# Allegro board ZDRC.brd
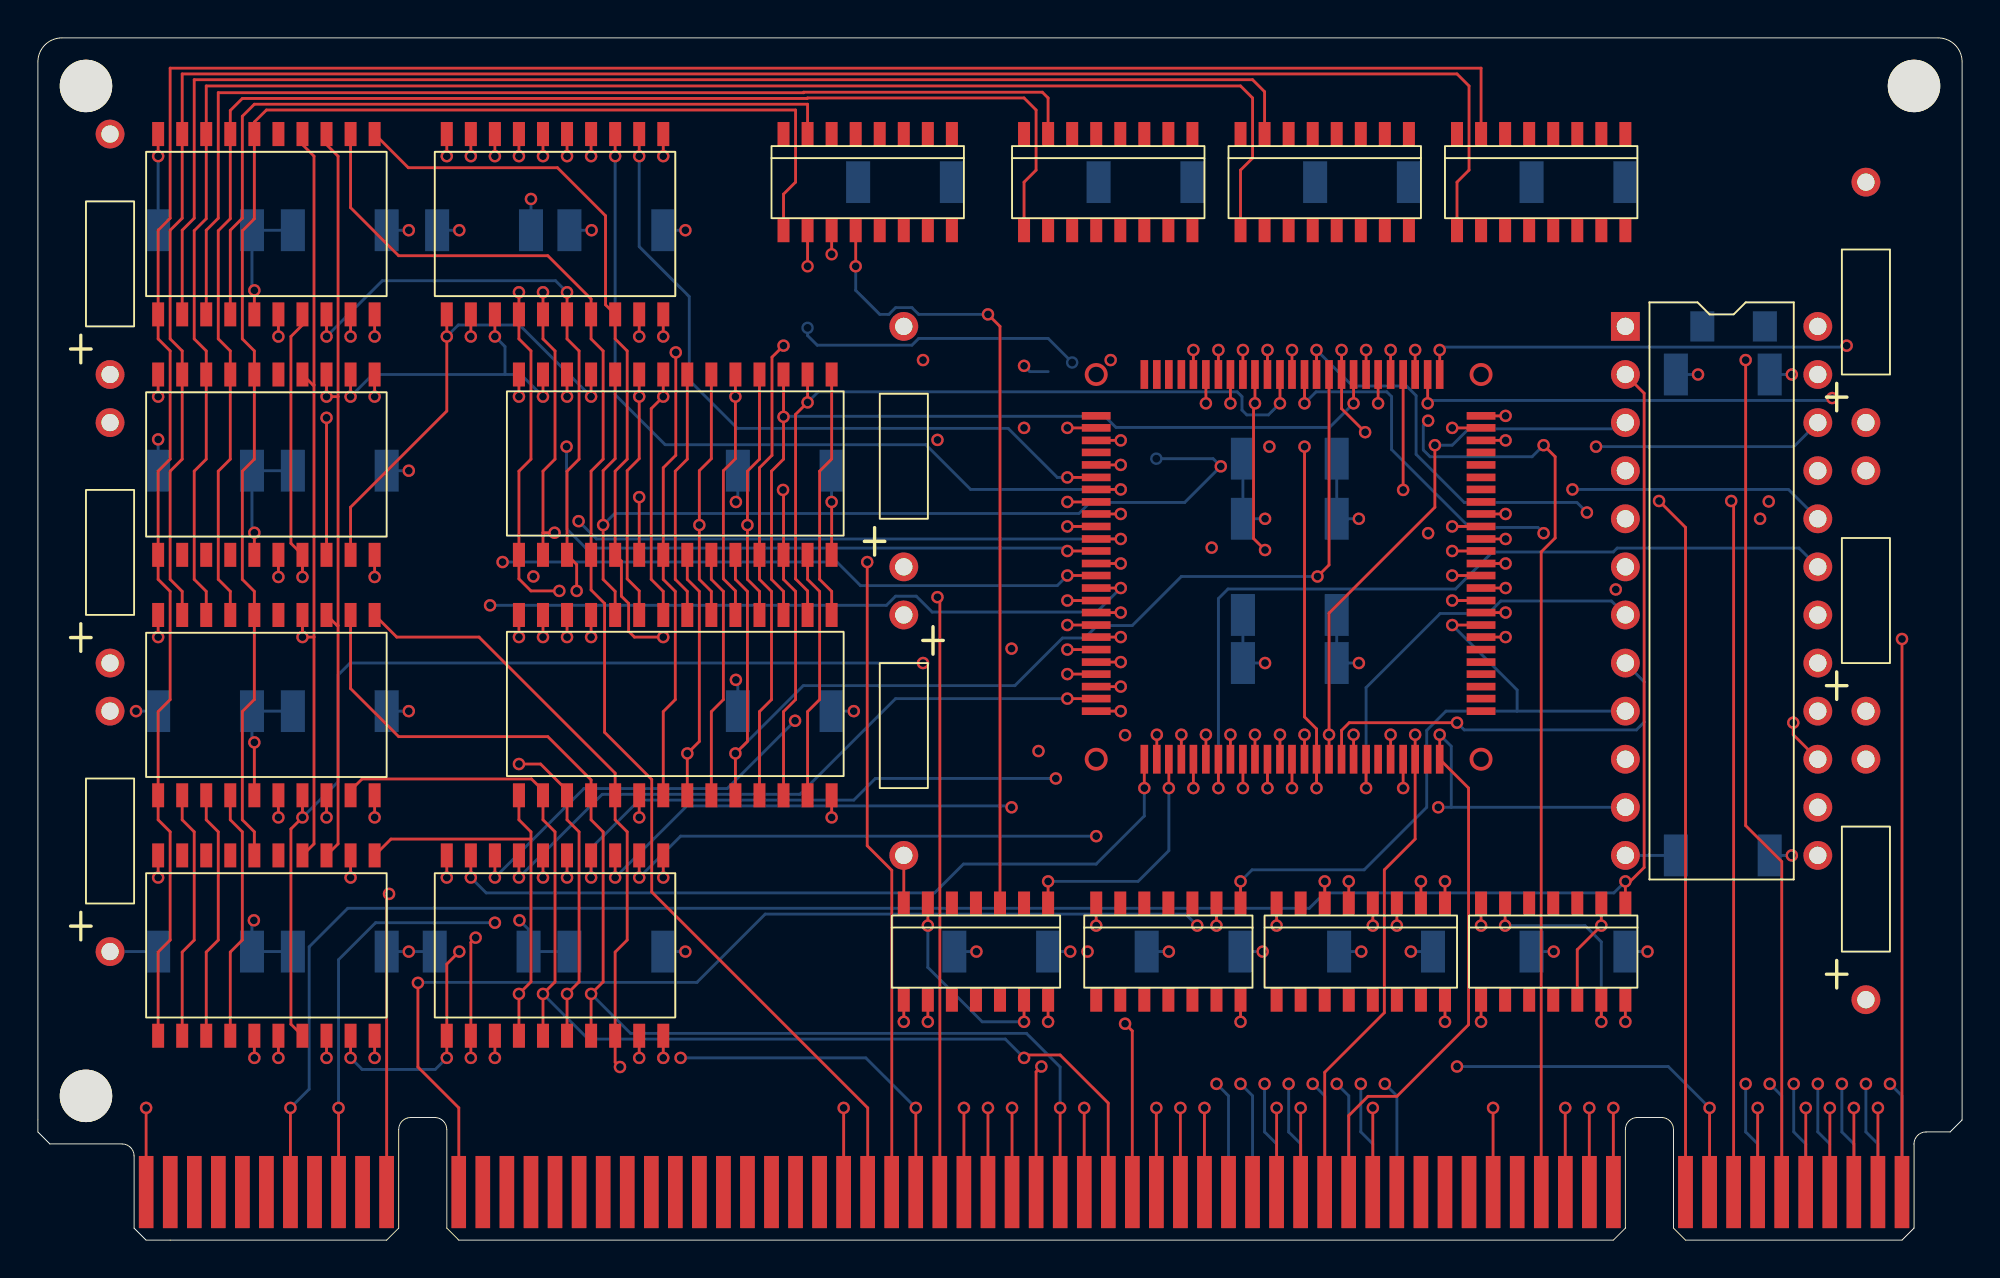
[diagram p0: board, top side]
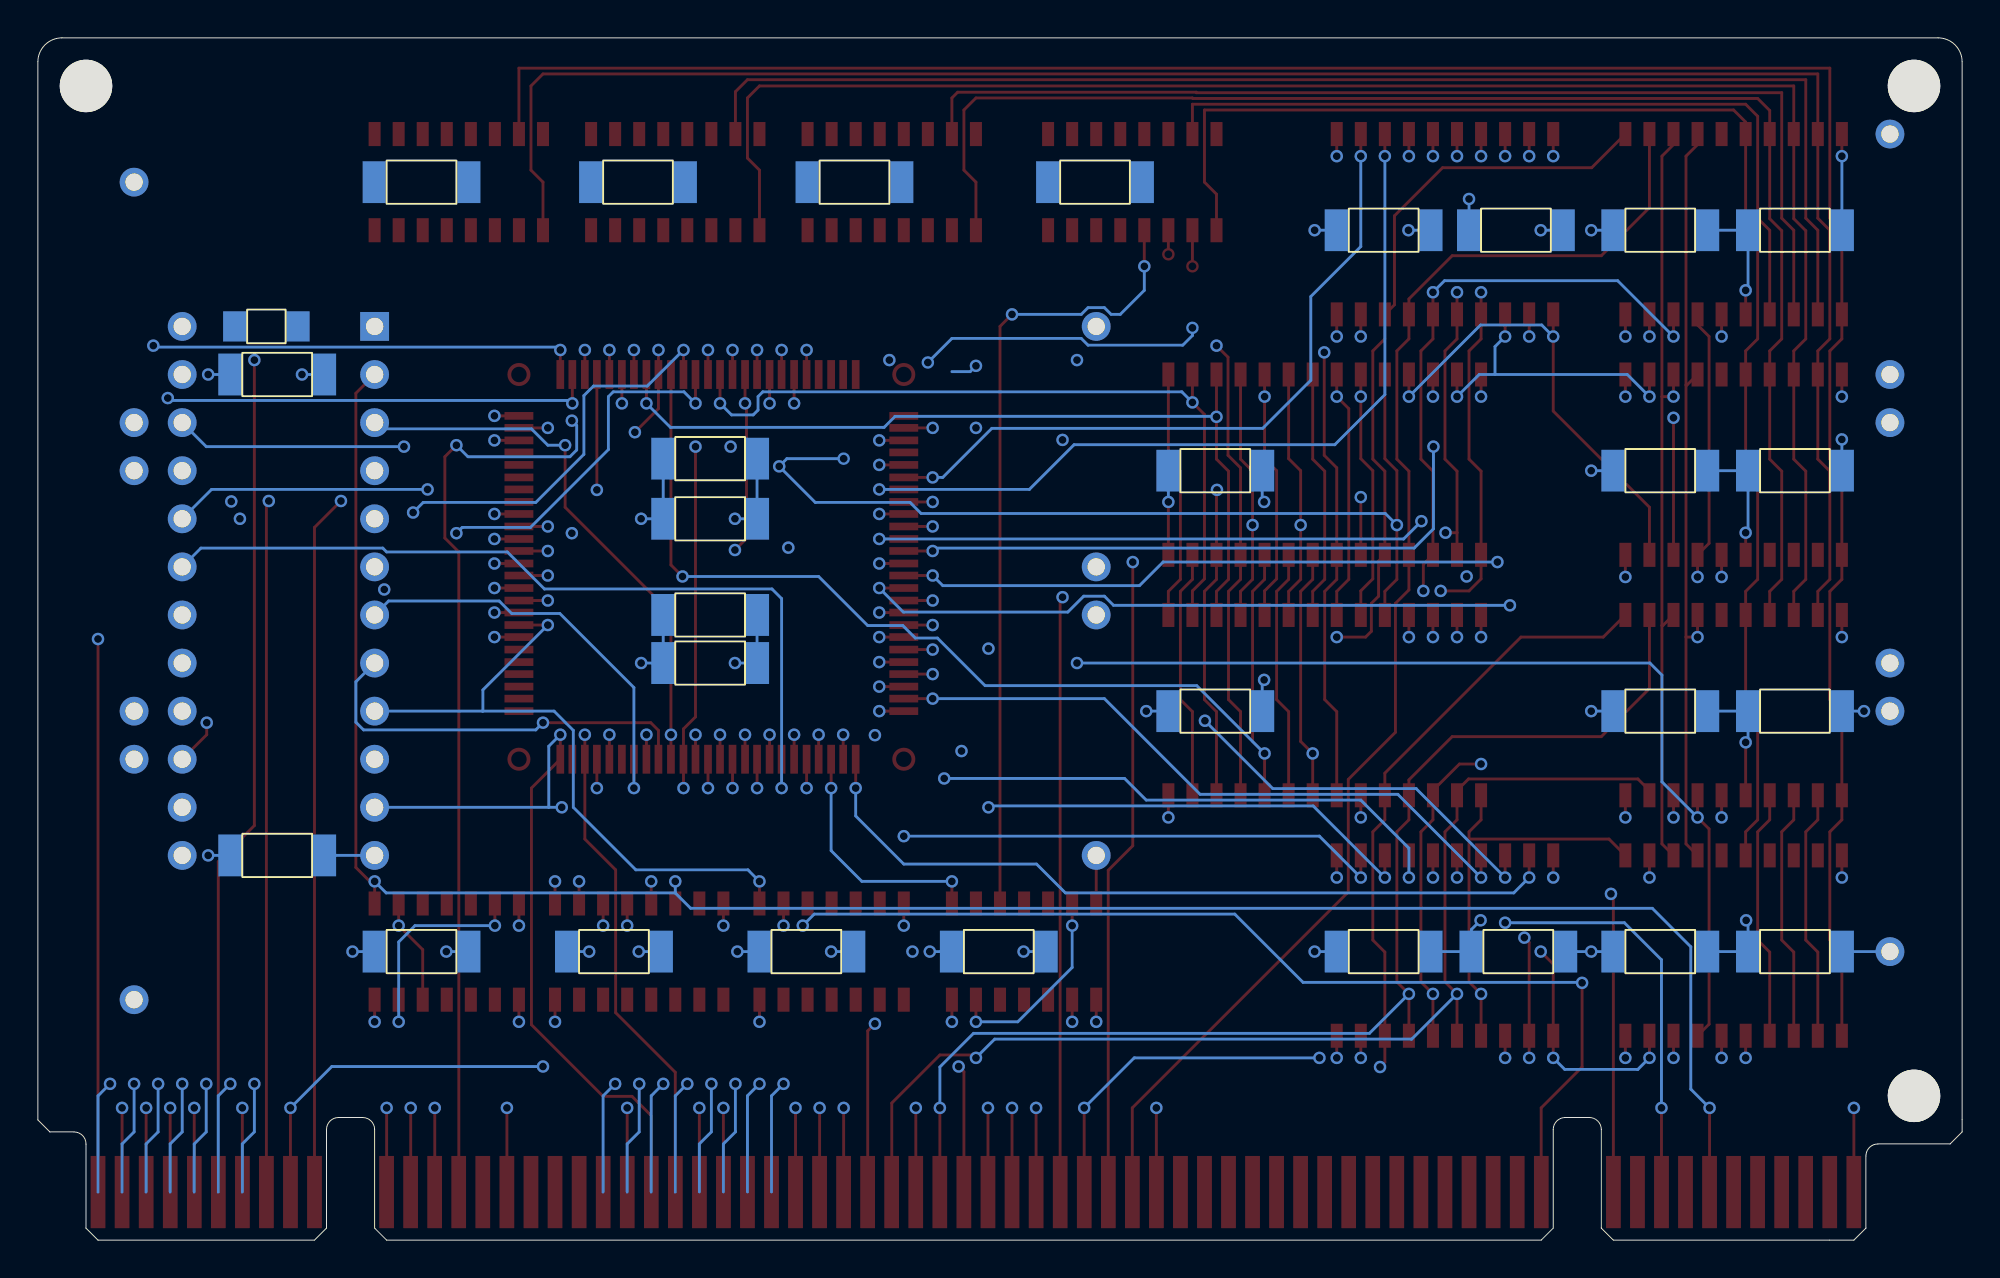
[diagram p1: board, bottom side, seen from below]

Outline 101.6 x 63.5 mm; copper layers: TOP, GND, IS1, IS2, VCC, GND2, IS3, IS4, GND3, BOTTOM. Coordinates in mm from the lower left corner of the outline.
Outline path: 0,62.23 arc(0.37,63.13) 1.27,63.5 100.33,63.5 arc(101.23,63.13) 101.6,62.23 101.6,6.35 100.97,5.71 99.7,5.71 arc(99.25,5.53) 99.06,5.08 99.06,0.63 98.43,0 87,0 86.36,0.63 86.36,5.84 arc(86.17,6.29) 85.73,6.48 84.46,6.48 arc(84.01,6.29) 83.82,5.84 83.82,0.63 83.19,0 22.22,0 21.59,0.63 21.59,5.84 arc(21.4,6.29) 20.95,6.48 19.68,6.48 arc(19.24,6.29) 19.05,5.84 19.05,0.63 18.41,0 5.71,0 5.08,0.63 5.08,4.45 arc(4.89,4.89) 4.45,5.08 0.64,5.08 0,5.71 0,62.23

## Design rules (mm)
constraint set DEFAULT: min track width 0.152
net group A_GROUP: nets A1 A2 A3 A4 A5 A6 A7 A8 A9 A10 A11 A12 A13 A14 A15 A16 A17 A18 A19 A20 A21 A22 A23
net group RA_GROUP: nets RA0 RA1 RA2 RA3 RA4 RA5 RA6 RA7

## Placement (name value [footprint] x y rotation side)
C1  0.01UF  [SMDCAP]  23.49 53.34 180 bottom
C2  0.01UF  [SMDCAP]  15.88 40.64 180 bottom
C3  0.01UF  [SMDCAP]  15.88 27.94 180 bottom
C4  0.01UF  [SMDCAP]  15.88 53.34 180 bottom
C5  0.01UF  [SMDCAP]  15.88 15.24 180 bottom
C6  0.01UF  [SMDCAP]  88.9 20.32 180 bottom
C7  0.01UF  [SMDCAP]  23.49 15.24 0 bottom
C8  0.01UF  [SMDCAP]  66.04 30.48 180 bottom
C9  0.01UF  [SMDCAP]  66.04 41.27 180 bottom
C10  0.01UF  [SMDCAP]  8.89 53.34 0 bottom
C11  0.01UF  [SMDCAP]  8.89 40.64 0 bottom
C12  0.01UF  [SMDCAP]  8.89 27.94 0 bottom
C13  0.01UF  [SMDCAP]  8.89 15.24 0 bottom
C14  0.01UF  [SMDCAP]  30.48 15.24 180 bottom
C15  0.01UF  [SMDCAP]  30.48 53.34 180 bottom
C16  0.01UF  [SMDCAP]  39.37 40.64 180 bottom
C17  0.01UF  [SMDCAP]  39.37 27.94 180 bottom
C18  0.01UF  [SMDCAP]  66.04 38.1 180 bottom
C19  0.01UF  [SMDCAP]  66.04 33.02 180 bottom
C20  0.01UF  [SMDCAP]  50.8 15.24 180 bottom
C21  0.022UF  [CAP400]  45.72 30.48 180 top
C22  0.022UF  [CAP400]  45.72 38.1 0 top
C23  0.022UF  [CAP400]  96.52 15.24 0 top
C24  0.022UF  [CAP400]  96.52 30.48 0 top
C25  0.022UF  [CAP400]  96.52 45.72 0 top
C26  0.022UF  [CAP400]  3.81 48.26 0 top
C27  0.022UF  [CAP400]  3.81 33.02 0 top
C28  0.022UF  [CAP400]  3.81 17.78 0 top
C29  1UF  [SMDCAP]  60.96 15.24 180 bottom
C30  1UF  [SMDCAP]  71.12 15.24 180 bottom
C31  1UF  [SMDCAP]  81.28 15.24 180 bottom
C32  1UF  [SMDCAP]  45.72 55.88 180 bottom
C33  1UF  [SMDCAP]  58.42 55.88 180 bottom
C34  1UF  [SMDCAP]  69.85 55.88 180 bottom
C35  1UF  [SMDCAP]  81.28 55.88 180 bottom
C36  1UF  [SMDCAP]  88.9 45.72 180 bottom
J1  -  [CONN140]  98.43 2.54 0 top
NOREF  -  [unnamed]  2.54 7.62 0 top
NOREF#2  -  [unnamed]  2.54 60.96 0 top
NOREF#3  -  [unnamed]  99.06 60.96 0 top
R1  10  [SMDRES]  89.54 48.26 180 bottom
U1  ***  [SOIC20W]  12.07 53.97 270 top
U2  ***  [SOIC20W]  12.07 41.27 270 top
U3  ***  [SOIC20W]  12.07 28.57 270 top
U4  ***  [SOIC20W]  12.07 15.88 270 top
U5  ***  [SOIC14]  59.69 15.24 270 top
U6  ***  [SOIC14]  49.53 15.24 270 top
U7  ***  [SOIC16]  69.85 15.24 270 top
U8  ***  [SOIC20W]  27.3 53.97 270 top
U9  ***  [SOIC20W]  27.3 15.88 270 top
U10  ***  [SOIC16]  43.81 55.88 270 top
U11  ***  [SOIC16]  79.38 55.88 270 top
U12  ***  [SOIC16]  56.52 55.88 270 top
U13  ***  [SOIC16]  67.95 55.88 270 top
U14  ***  [SOIC14]  80.01 15.24 270 top
U15  ***  [DIP24_4]  83.82 48.26 0 top
U16  ***  [SOIC28W]  33.66 41.27 270 top
U17  -  [FLAT100]  58.42 25.4 270 top
U18  ***  [SOIC28W]  33.66 28.57 270 top

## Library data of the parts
C1-C20 = CAP-.01UF: User Part Number: 1206; Tolerance: ***
C21-C28 = CAP-22UF: User Part Number: 21505-274-01; Tolerance: ***
C29-C36 = CAP-1UF: User Part Number: 21503-260-12; Tolerance: ***
J1 = CONN140-1
R1 = PRES-10: User Part Number: 24707-008-01; Tolerance: ***
U1-U4 = M5M44C256P-10-1
U5 = 74F04-1
U6 U14 = 74F393-1
U7 = 74F109-1
U8 U9 = 74F245-1
U10-U13 = 74F153-1
U15 = MEMPAL-1
U16 U18 = 27C256-1
U17 = I80386S-1

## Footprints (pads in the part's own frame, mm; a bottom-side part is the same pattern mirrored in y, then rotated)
CAP400
  round 1.524 hole 0.914: 1(0,-2.54) 2(0,10.16)
CONN140
  rect 0.762x3.81 smd: 1(0,0) 2(-1.27,0) 3(-2.54,0) 4(-3.81,0) 5(-5.08,0) 6(-6.35,0) 7(-7.62,0) 8(-8.89,0) 9(-10.16,0) 10(-11.43,0) 11(-15.24,0) 12(-16.51,0) 13(-17.78,0) 14(-19.05,0) 15(-20.32,0) 16(-21.59,0) 17(-22.86,0) 18(-24.13,0) 19(-25.4,0) 20(-26.67,0) 21(-27.94,0) 22(-29.21,0) 23(-30.48,0) 24(-31.75,0) 25(-33.02,0) 26(-34.29,0) 27(-35.56,0) 28(-36.83,0) 29(-38.1,0) 30(-39.37,0) 31(-40.64,0) 32(-41.91,0) 33(-43.18,0) 34(-44.45,0) 35(-45.72,0) 36(-46.99,0) 37(-48.26,0) 38(-49.53,0) 39(-50.8,0) 40(-52.07,0) 41(-53.34,0) 42(-54.61,0) 43(-55.88,0) 44(-57.15,0) 45(-58.42,0) 46(-59.69,0) 47(-60.96,0) 48(-62.23,0) 49(-63.5,0) 50(-64.77,0) 51(-66.04,0) 52(-67.31,0) 53(-68.58,0) 54(-69.85,0) 55(-71.12,0) 56(-72.39,0) 57(-73.66,0) 58(-74.93,0) 59(-76.2,0) 60(-80.01,0) 61(-81.28,0) 62(-82.55,0) 63(-83.82,0) 64(-85.09,0) 65(-86.36,0) 66(-87.63,0) 67(-88.9,0) 68(-90.17,0) 69(-91.44,0) 70(-92.71,0) 71(0,0) 72(-1.27,0) 73(-2.54,0) 74(-3.81,0) 75(-5.08,0) 76(-6.35,0) 77(-7.62,0) 78(-8.89,0) 79(-10.16,0) 80(-11.43,0) 81(-15.24,0) 82(-16.51,0) 83(-17.78,0) 84(-19.05,0) 85(-20.32,0) 86(-21.59,0) 87(-22.86,0) 88(-24.13,0) 89(-25.4,0) 90(-26.67,0) 91(-27.94,0) 92(-29.21,0) 93(-30.48,0) 94(-31.75,0) 95(-33.02,0) 96(-34.29,0) 97(-35.56,0) 98(-36.83,0) 99(-38.1,0) 100(-39.37,0) 101(-40.64,0) 102(-41.91,0) 103(-43.18,0) 104(-44.45,0) 105(-45.72,0) 106(-46.99,0) 107(-48.26,0) 108(-49.53,0) 109(-50.8,0) 110(-52.07,0) 111(-53.34,0) 112(-54.61,0) 113(-55.88,0) 114(-57.15,0) 115(-58.42,0) 116(-59.69,0) 117(-60.96,0) 118(-62.23,0) 119(-63.5,0) 120(-64.77,0) 121(-66.04,0) 122(-67.31,0) 123(-68.58,0) 124(-69.85,0) 125(-71.12,0) 126(-72.39,0) 127(-73.66,0) 128(-74.93,0) 129(-76.2,0) 130(-80.01,0) 131(-81.28,0) 132(-82.55,0) 133(-83.82,0) 134(-85.09,0) 135(-86.36,0) 136(-87.63,0) 137(-88.9,0) 138(-90.17,0) 139(-91.44,0) 140(-92.71,0)
DIP24_4
  rect 1.524x1.524 hole 0.914: 1(0,0)
  round 1.524 hole 0.914: 2(0,-2.54) 3(0,-5.08) 4(0,-7.62) 5(0,-10.16) 6(0,-12.7) 7(0,-15.24) 8(0,-17.78) 9(0,-20.32) 10(0,-22.86) 11(0,-25.4) 12(0,-27.94) 13(10.16,-27.94) 14(10.16,-25.4) 15(10.16,-22.86) 16(10.16,-20.32) 17(10.16,-17.78) 18(10.16,-15.24) 19(10.16,-12.7) 20(10.16,-10.16) 21(10.16,-7.62) 22(10.16,-5.08) 23(10.16,-2.54) 24(10.16,0)
FLAT100
  rect 1.524x0.406 smd: 1(0,0) 2(0,0.66) 3(0,1.295) 4(0,1.956) 5(0,2.591) 6(0,3.251) 7(0,3.912) 8(0,4.547) 9(0,5.207) 10(0,5.842) 11(0,6.502) 12(0,7.163) 13(0,7.798) 14(0,8.458) 15(0,9.093) 16(0,9.754) 17(0,10.414) 18(0,11.049) 19(0,11.709) 20(0,12.344) 21(0,13.005) 22(0,13.665) 23(0,14.3) 24(0,14.961) 25(0,15.596) 51(-20.32,15.596) 52(-20.32,14.961) 53(-20.32,14.3) 54(-20.32,13.665) 55(-20.32,13.005) 56(-20.32,12.344) 57(-20.32,11.709) 58(-20.32,11.049) 59(-20.32,10.414) 60(-20.32,9.754) 61(-20.32,9.093) 62(-20.32,8.458) 63(-20.32,7.798) 64(-20.32,7.163) 65(-20.32,6.502) 66(-20.32,5.842) 67(-20.32,5.207) 68(-20.32,4.547) 69(-20.32,3.912) 70(-20.32,3.251) 71(-20.32,2.591) 72(-20.32,1.956) 73(-20.32,1.295) 74(-20.32,0.66) 75(-20.32,0)
  rect 0.406x1.524 smd: 26(-2.54,17.78) 27(-3.2,17.78) 28(-3.835,17.78) 29(-4.496,17.78) 30(-5.131,17.78) 31(-5.791,17.78) 32(-6.452,17.78) 33(-7.087,17.78) 34(-7.747,17.78) 35(-8.382,17.78) 36(-9.042,17.78) 37(-9.703,17.78) 38(-10.338,17.78) 39(-10.998,17.78) 40(-11.633,17.78) 41(-12.294,17.78) 42(-12.954,17.78) 43(-13.589,17.78) 44(-14.249,17.78) 45(-14.884,17.78) 46(-15.545,17.78) 47(-16.205,17.78) 48(-16.84,17.78) 49(-17.501,17.78) 50(-18.136,17.78) 76(-18.136,-2.54) 77(-17.501,-2.54) 78(-16.84,-2.54) 79(-16.205,-2.54) 80(-15.545,-2.54) 81(-14.884,-2.54) 82(-14.249,-2.54) 83(-13.589,-2.54) 84(-12.954,-2.54) 85(-12.294,-2.54) 86(-11.633,-2.54) 87(-10.998,-2.54) 88(-10.338,-2.54) 89(-9.703,-2.54) 90(-9.042,-2.54) 91(-8.382,-2.54) 92(-7.747,-2.54) 93(-7.087,-2.54) 94(-6.452,-2.54) 95(-5.791,-2.54) 96(-5.131,-2.54) 97(-4.496,-2.54) 98(-3.835,-2.54) 99(-3.2,-2.54) 100(-2.54,-2.54)
SMDCAP
  rect 1.27x2.21 smd: 1(-2.54,0) 2(2.413,0)
SMDRES
  rect 1.27x1.6 smd: 1(-1.651,0) 2(1.651,0)
SOIC14
  rect 1.27x0.635 smd: 1(-2.54,3.81) 2(-2.54,2.54) 3(-2.54,1.27) 4(-2.54,0) 5(-2.54,-1.27) 6(-2.54,-2.54) 7(-2.54,-3.81) 8(2.54,-3.81) 9(2.54,-2.54) 10(2.54,-1.27) 11(2.54,0) 12(2.54,1.27) 13(2.54,2.54) 14(2.54,3.81)
SOIC16
  rect 1.27x0.635 smd: 1(-2.54,4.445) 2(-2.54,3.175) 3(-2.54,1.905) 4(-2.54,0.635) 5(-2.54,-0.635) 6(-2.54,-1.905) 7(-2.54,-3.175) 8(-2.54,-4.445) 9(2.54,-4.445) 10(2.54,-3.175) 11(2.54,-1.905) 12(2.54,-0.635) 13(2.54,0.635) 14(2.54,1.905) 15(2.54,3.175) 16(2.54,4.445)
SOIC20W
  rect 1.27x0.635 smd: 1(-4.445,5.715) 2(-4.445,4.445) 3(-4.445,3.175) 4(-4.445,1.905) 5(-4.445,0.635) 6(-4.445,-0.635) 7(-4.445,-1.905) 8(-4.445,-3.175) 9(-4.445,-4.445) 10(-4.445,-5.715) 11(5.08,-5.715) 12(5.08,-4.445) 13(5.08,-3.175) 14(5.08,-1.905) 15(5.08,-0.635) 16(5.08,0.635) 17(5.08,1.905) 18(5.08,3.175) 19(5.08,4.445) 20(5.08,5.715)
SOIC28W
  rect 1.27x0.635 smd: 1(-4.445,8.255) 2(-4.445,6.985) 3(-4.445,5.715) 4(-4.445,4.445) 5(-4.445,3.175) 6(-4.445,1.905) 7(-4.445,0.635) 8(-4.445,-0.635) 9(-4.445,-1.905) 10(-4.445,-3.175) 11(-4.445,-4.445) 12(-4.445,-5.715) 13(-4.445,-6.985) 14(-4.445,-8.255) 15(5.08,-8.255) 16(5.08,-6.985) 17(5.08,-5.715) 18(5.08,-4.445) 19(5.08,-3.175) 20(5.08,-1.905) 21(5.08,-0.635) 22(5.08,0.635) 23(5.08,1.905) 24(5.08,3.175) 25(5.08,4.445) 26(5.08,5.715) 27(5.08,6.985) 28(5.08,8.255)
unnamed
  round 2.769 hole 2.769 unplated: (0,0)

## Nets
GND: C1.2(B<0>) C2.2(B<0>) C3.2(B<0>) C4.2(B<0>) C5.2(B<0>) C6.2(B<0>) C7.2(B<0>) C8.2(B<0>) C9.2(B<0>) C10.2(B<0>) C11.2(B<0>) C12.2(B<0>) C13.2(B<0>) C14.2(B<0>) C15.2(B<0>) C16.2(B<0>) C17.2(B<0>) C18.2(B<0>) C19.2(B<0>) C20.2(B<0>) C21.2(B<0>) C22.2(B<0>) C23.2(B<0>) C24.2(B<0>) C25.2(B<0>) C26.2(B<0>) C27.2(B<0>) C28.2(B<0>) C29.2(B<0>) C30.2(B<0>) C31.2(B<0>) C32.2(B<0>) C33.2(B<0>) C34.2(B<0>) C35.2(B<0>) C36.2(B<0>) J1.90 J1.91 J1.92 J1.93 J1.94 J1.95 J1.96 J1.97 U1.15 U1.16 U1.20 U2.15 U2.16 U2.20 U3.15 U3.16 U3.20 U4.15 U4.16 U4.20 U5.7 U6.7 U7.3 U7.8 U8.10 U8.19 U9.10 U9.19 U10.1 U10.8 U10.15 U11.1 U11.8 U11.15 U12.1 U12.8 U12.15 U13.1 U13.8 U13.15 U14.7 U15.12 U15.13 U16.14 U16.20 U17.2 U17.5 U17.11 U17.12 U17.13 U17.14 U17.22 U17.35 U17.37 U17.38 U17.40 U17.41 U17.49 U17.50 U17.63 U17.67 U17.68 U17.77 U17.78 U17.85 U17.98 U18.14 U18.20
VCC: C1.1 C2.1 C3.1 C4.1 C5.1 C6.1 C7.1 C8.1 C9.1 C10.1 C11.1 C12.1 C13.1 C14.1 C15.1 C16.1 C17.1 C18.1 C19.1 C20.1 C21.1 C22.1 C23.1 C24.1 C25.1 C26.1 C27.1 C28.1 C29.1 C30.1 C31.1 C32.1 C33.1 C34.1 C35.1 C36.1 J1.70 J1.71 J1.72 J1.73 J1.74 J1.75 J1.76 J1.77 U1.10 U2.10 U3.10 U4.10 U5.14 U6.14 U7.1 U7.2 U7.16 U8.20 U9.20 U10.16 U11.16 U12.16 U13.16 U14.14 U15.24 U16.28 U17.6 U17.8 U17.9 U17.10 U17.21 U17.32 U17.34 U17.36 U17.39 U17.42 U17.48 U17.57 U17.69 U17.71 U17.84 U17.91 U17.97 U18.28
A1: J1.2 U10.10 U16.10 U17.18 U18.10
A2: J1.3 U12.10 U16.9 U17.51 U18.9
A3: J1.4 U13.10 U16.8 U17.52 U18.8
A4: J1.5 U11.10 U16.7 U17.53 U18.7
A5: J1.6 U11.6 U16.6 U17.54 U18.6
A6: J1.7 U13.6 U16.5 U17.55 U18.5
A7: J1.8 U12.6 U16.4 U17.56 U18.4
A8: J1.9 U10.6 U16.3 U17.58 U18.3
A9: J1.10 U10.11 U16.25 U17.59 U18.25
A10: J1.11 U12.11 U16.24 U17.60 U18.24
A11: J1.12 U13.11 U16.21 U17.61 U18.21
A12: J1.13 U11.11 U16.23 U17.62 U18.23
A13: J1.14 U11.5 U16.2 U17.64 U18.2
A14: J1.15 U13.5 U16.26 U17.65 U18.26
A15: J1.16 U12.5 U16.27 U17.66 U18.27
A16: U10.5 U17.70
A17: U17.72
A18: U17.73
A19: U17.74
A20: U17.75
A21: U17.76
A22: U17.79
A23: U15.6 U17.80
ADDR0: U1.6 U2.6 U3.6 U4.6 U10.9(Y<0>)
ADDR1: U1.7 U2.7 U3.7 U4.7 U12.9(Y<0>)
ADDR2: U1.8 U2.8 U3.8 U4.8 U13.9(Y<0>)
ADDR3: U1.9 U2.9 U3.9 U4.9 U11.9(Y<0>)
ADDR4: U1.11 U2.11 U3.11 U4.11 U11.7
ADDR5: U1.12 U2.12 U3.12 U4.12 U13.7
ADDR6: U1.13 U2.13 U3.13 U4.13 U12.7
ADDR7: U1.14 U2.14 U3.14 U4.14 U10.7
ADSL: J1.24 U15.3 U17.16
BHEL: J1.21 U15.7 U17.19
BLEL: J1.1(P<0>) U15.8 U17.17
CAS0L: U3.17 U4.17 U15.17
CAS1L: U1.17 U2.17 U15.18
CLK2: J1.62 R1.2(B<0>) U7.4 U15.1 U17.15
CLRCNT: U14.2 U14.12 U15.21
D0: U9.9 U17.1
D1: U9.8 U17.100
D2: U9.7 U17.99
D3: U9.6 U17.96
D4: U9.5 U17.95
D5: U9.4 U17.94
D6: U9.3 U17.93
D7: U9.2 U17.92
D8: U8.9 U17.90
D9: U8.8 U17.89
D10: U8.7 U17.88
D11: U8.6 U17.87
D12: U8.5 U17.86
D13: U8.4 U17.83
D14: U8.3 U17.82
D15: U8.2 U17.81
DATA0: J1.28 U4.19(DQ<0>) U9.11(B<0>) U18.11
DATA1: J1.29 U4.18 U9.12 U18.12
DATA2: J1.30 U4.2 U9.13 U18.13
DATA3: J1.31 U4.1 U9.14 U18.15
DATA4: J1.32 U3.19(DQ<0>) U9.15 U18.16
DATA5: J1.33 U3.18 U9.16 U18.17
DATA6: J1.34 U3.2 U9.17 U18.18
DATA7: J1.35 U3.1 U9.18 U18.19
DATA8: J1.36 U2.19(DQ<0>) U8.11(B<0>) U16.11
DATA9: J1.37 U2.18 U8.12 U16.12
DATA10: J1.38 U2.2 U8.13 U16.13
DATA11: J1.39 U2.1 U8.14 U16.15
DATA12: J1.40 U1.19(DQ<0>) U8.15 U16.16
DATA13: J1.41 U1.18 U8.16 U16.17
DATA14: J1.42 U1.2 U8.17 U16.18
DATA15: J1.43 U1.1 U8.18 U16.19
HLDA: J1.25 U6.1 U10.2 U11.2 U12.2 U13.2 U15.4 U17.3
MIO: J1.23 U15.5 U17.23
MUXS0L: U10.14 U11.14 U12.14 U13.14 U15.20
PCLK: J1.64 U7.6 U14.1 U15.2
RA0: U6.3 U10.12
RA1: U6.4 U12.12
RA2: U6.5 U13.12
RA3: U6.6 U6.13 U11.12
RA4: U6.11 U11.4
RA5: U6.10 U13.4
RA6: U6.9 U12.4
RA7: U6.8(Q<3>) U10.4
RASL: U1.4 U2.4 U3.4 U4.4 U15.16
RDYL: J1.60 U15.19 U17.7
REF: U14.8(Q<3>) U15.10 U17.4
RESET: J1.59 U5.1 U15.9 U17.33(RESET)
RESETL: U5.2 U7.5
ROMOEL: U15.15 U16.22 U18.22
UN1F39330PQ0: U14.6 U14.13
UN1OSC1PB0: R1.1
UN127C25637PVPP0: U16.1(VPP) U18.1(VPP)
WEL: U1.3 U2.3 U3.3 U4.3 U15.22
WR: J1.22 U8.1 U9.1 U15.11(I<9>) U17.25

Pads without a net: J1 17 18 19 20 26 27 44 45 46 47 48 49 50 51 52 53 54 55 56 57 58 61 63 65 66 67 68 69 78 79 80 81 82 83 84 85 86 87 88 89 98 99 100 101 102 103 104 105 106 107 108 109 110 111 112 113 114 115 116 117 118 119 120 121 122 123 124 125 126 127 128 129 130 131 132 133 134 135 136 137 138 139 140; U1 5; U2 5; U3 5; U4 5; U5 3 4 5 6 8 9 10 11 12 13; U6 2 12; U7 7 9 10 11 12 13 14 15; U10 3 13; U11 3 13; U12 3 13; U13 3 13; U14 3 4 5 9 10 11; U15 14 23; U17 20 24 26 27 28 29 30 31 43 44 45 46 47

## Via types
v1: diameter 0.66, hole 0.406, TOP to BOTTOM, 332 vias
v2: diameter 0.66, hole 0.406, TOP to IS1, 4 vias
v3: diameter 0.66, hole 0.406, IS1 to IS2, 3 vias
v4: diameter 0.66, hole 0.406, IS2 to IS3, 3 vias
v5: diameter 0.66, hole 0.406, IS3 to IS4, 3 vias
v6: diameter 0.66, hole 0.406, IS4 to BOTTOM, 5 vias

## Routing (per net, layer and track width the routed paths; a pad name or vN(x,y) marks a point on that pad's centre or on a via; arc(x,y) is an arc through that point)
GND: length 157
  TOP w0.152: v1(62.97,44.2) U17.68 ; v1(55.88,16.61) U5.7 ; v1(31.75,9.63) U9.19 ; v1(74.68,35.1) U17.37 ; U17.2 v1(59.08,26.7) ; v1(31.75,47.73) U8.19 ; v1(12.7,9.63) U4.16 ; v1(12.7,47.73) U1.16 ; 11.43,23.5 v1(11.43,26.29) ; U17.50 v1(77.5,43.54) ; v1(31.75,22.33) 31.75,23.5 ; v1(76.2,16.61) U14.7 ; v1(25.4,44.55) U16.14 ; U17.40 v1(77.5,37.03) ; v1(74.68,33.78) U17.35 ; U2.15 v1(11.43,37.36) ; v1(17.78,22.33) 17.78,23.5 ; U17.14 v1(66.88,26.7) ; v1(65.41,16.61) U7.8 ; v1(54.36,42.9) U17.77 ; U16.20 v1(31.75,39.24) ; U17.67 v1(63.63,47.02) ; U17.12 v1(65.58,26.7) ; v1(74.68,37.69) U17.41 ; v1(74.68,42.9) U17.49 ; v1(11.43,9.63) U4.15 ; v1(12.7,35.03) U2.16 ; v1(54.36,37.69) U17.85 ; v1(64.92,23.88) U17.11 ; v1(72.09,23.88) U17.22 ; v1(61.01,23.88) U17.5 ; v1(21.59,57.25) U8.10 ; v1(17.78,9.63) U4.20 ; v1(71.76,16.61) U7.3 ; v1(66.22,23.88) U17.13 ; v1(17.78,47.73) U1.20 ; v1(12.7,22.33) 12.7,23.5 ; U17.38 v1(77.5,35.74) ; v1(17.78,35.03) U2.20 ; U17.78 v1(57.18,42.24) ; U17.63 v1(66.22,47.02) ; v1(21.59,19.15) U9.10 ; U17.98 v1(57.18,29.24) ; U6.7 C21.2 ; U1.15 v1(11.43,50.16) ; v1(25.4,31.85) U18.14
  GND w0.152: v1(36.86,29.59) 36.96,29.59 ; v1(36.86,38.99) 36.96,38.99 ; 11.3,16.89 v1(11.4,16.89)
  BOTTOM w0.152: v1(71.12,8.26) 71.76,7.62 J1.90 ; v1(69.85,8.26) 69.85,5.71 70.48,5.08 70.48,2.54 ; J1.93 67.95,7.62 v1(67.31,8.26) ; v1(64.77,8.26) 64.77,5.71 65.41,5.08 J1.95 ; v1(25.43,16.89) 25.91,16.41 C7.2 C14.2 ; C30.2 v1(69.88,15.24) ; C9.2 C18.2 v1(64.8,38.1) ; v1(11.4,16.89) 11.3,16.79 C13.2 C5.2 ; C17.2 36.96,29.49 v1(36.86,29.59) ; v1(36.86,38.99) 36.96,39.09 C16.2 ; C31.2 v1(80.04,15.24) ; J1.92 69.22,7.62 v1(68.58,8.26) ; J1.94 66.68,5.08 66.04,5.71 v1(66.04,8.26) ; v1(63.5,8.26) 64.14,7.62 J1.96 ; C29.2 v1(59.72,15.24) ; C36.2 v1(87.66,45.72) ; v1(11.43,37.36) 11.3,37.49 C11.2 C2.2 ; C15.2 v1(29.24,53.34) ; v1(11.43,50.16) 11.3,50.16 C10.2 C4.2 ; C3.2 C12.2 11.3,26.42 v1(11.43,26.29) ; U15.12 C6.2 ; J1.97 62.87,7.62 v1(62.23,8.26) ; v1(64.8,30.48) C8.2 C19.2 ; C20.2 v1(49.56,15.24) ; C1.2 v1(22.25,53.34)
VCC: length 124.4
  TOP w0.152: U17.84 v1(57.18,38.35) ; U7.1 v1(74.3,18.95) ; U17.48 v1(77.5,42.24) ; v1(6.35,44.55) U2.10 ; v1(74.68,36.4) U17.39 ; U17.6 v1(61.67,26.7) ; U17.36 v1(77.5,34.44) ; U17.32 v1(77.5,31.85) ; v1(63.63,23.88) U17.9 ; U17.8 v1(62.97,26.7) ; U17.57 v1(70.13,47.02) ; v1(54.36,29.9) U17.97 ; U17.21 v1(71.42,26.7) ; v1(74.3,11.53) U7.16 ; v1(33.02,47.73) U8.20 ; U17.34 v1(77.5,33.15) ; v1(33.02,9.63) U9.20 ; v1(41.91,22.33) 41.91,23.5 ; v1(6.35,19.15) U4.10 ; J1.70 v1(5.71,6.99) ; v1(53.34,11.53) U6.14 ; U17.10 v1(64.26,26.7) ; U7.2 v1(73.03,18.95) ; U16.28 v1(41.91,38.99) ; U17.42 v1(77.5,38.35) ; v1(6.35,31.85) U3.10 ; v1(6.35,57.25) U1.10 ; v1(63.5,11.53) U5.14 ; U17.69 v1(62.33,47.02) ; v1(83.82,11.53) U14.14 ; U17.71 v1(61.01,47.02) ; v1(54.36,33.78) U17.91
  BOTTOM w0.152: v1(90.17,8.26) 90.17,5.71 90.81,5.08 J1.77 ; C4.1 v1(19.58,53.34) ; v1(5.18,27.94) C12.1 ; C5.1 v1(19.58,15.24) C7.1 ; C11.1 v1(6.35,42.29) ; C20.1 v1(54.51,15.24) ; C10.1 v1(6.35,57.25) ; J1.76 92.08,7.62 v1(91.44,8.26) ; v1(93.98,8.26) 93.98,5.71 94.62,5.08 J1.74 ; v1(96.52,8.26) 96.52,5.71 97.16,5.08 J1.72 ; 26.04,53.34 v1(26.04,54.99) ; v1(69.75,38.1) C18.1 C9.1 ; C29.1 v1(64.67,15.24) ; v1(97.79,8.26) 98.43,7.62 J1.71 ; v1(95.25,8.26) 95.25,5.71 95.89,5.08 J1.73 ; C6.1 v1(92.61,20.32) ; C2.1 v1(19.58,40.64) ; C36.1 v1(92.61,45.72) ; C15.1 v1(34.19,53.34) ; v1(72.49,15.24) C30.1 ; C14.1 v1(34.19,15.24) ; C31.1 v1(84.99,15.24) ; v1(41.91,38.99) C16.1 ; C28.1 C13.1 ; v1(69.75,30.48) C8.1 C19.1 ; C17.1 v1(43.08,27.94) ; v1(92.71,8.26) 92.71,5.71 93.35,5.08 J1.75 ; C3.1 v1(19.58,27.94)
A1: length 152.9
  TOP w0.152: U17.18 v1(69.47,26.7) ; U16.10 30.48,41.27 29.84,40.64 v1(29.84,37.77) 29.84,34.9 30.48,34.26 U18.10 ; J1.2 v1(97.16,6.99) ; U10.10 v2(40.64,51.43)
  IS1 w0.152: v2(40.64,51.43) v3(40.64,50.62) ; v1(69.47,26.7) 70.08,26.09 83.16,26.09 83.41,26.34 96.95,26.34 97.46,25.83 97.46,8.79 97.16,8.48 v1(97.16,6.99)
  IS2 w0.152: v1(62.46,40.87) 66.27,40.87 66.27,29.9 v1(69.47,26.7) ; v3(40.64,50.62) v4(40.64,49.81)
  IS3 w0.152: v4(40.64,49.81) v5(40.64,49)
  IS4 w0.152: v6(54.61,46.35) 54.61,44.45 55.24,43.81 55.24,41.43 55.4,41.27 56.69,41.27 56.92,41.5 58.83,41.5 v6(59.05,41.27) ; v5(40.64,49) v6(40.64,48.18)
  BOTTOM w0.152: v6(54.61,46.35) 53.34,47.62 46.51,47.62 46.15,47.27 41.15,47.27 40.64,47.78 v6(40.64,48.18) ; v1(29.84,37.77) 30.45,38.38 54.97,38.38 55.55,38.96 60.55,38.96 v1(62.46,40.87) 62.05,41.27 v6(59.05,41.27)
A2: length 81
  TOP w0.152: J1.3 v1(95.89,6.99) ; U18.9 31.75,34.29 31.11,34.92 31.11,40.64 31.75,41.27 v1(31.75,44.55) U16.9 ; U17.51 v1(74.02,47.02)
  IS2 w0.152: v1(95.89,6.99) 95.89,11.99 95.5,12.37 v1(95.5,47.24)
  BOTTOM w0.152: v1(74.02,47.02) 74.17,47.17 95.43,47.17 v1(95.5,47.24)
A3: length 99.6
  TOP w0.152: U18.8 33.02,34.26 32.38,34.9 32.38,43.92 v1(33.02,44.55) U16.8 ; J1.4 v1(94.62,6.99) ; v1(73.38,44.2) U17.52
  IS1 w0.152: v1(52.07,46.18) 51.44,45.54 34.01,45.54 v1(33.02,44.55)
  IS2 w0.152: v1(94.62,6.99) 94.62,19.61 94.92,19.91 94.92,44.3 v1(94.74,44.48)
  BOTTOM w0.152: v1(73.38,44.2) 73.38,44.35 94.62,44.35 v1(94.74,44.48) ; 53.34,45.87 52.37,45.87 v1(52.07,46.18)
A4: length 75.3
  TOP w0.152: U16.7 34.29,41.25 33.66,40.61 33.66,34.9 34.29,34.26 U18.7 ; J1.5 v1(93.35,6.99) ; U17.53 v1(72.72,47.02)
  IS1 w0.152: v1(72.72,47.02) 73.33,46.41 81.64,46.41 83.29,44.75 88.19,44.75 91.39,41.55 v1(91.39,39.01)
  IS2 w0.152: v1(91.39,39.01) 92,38.4 92,9.88 93.35,8.53 v1(93.35,6.99)
A5: length 102
  TOP w0.152: v1(90.17,46.48) 90.17,21.89 92.08,19.99 J1.6 ; U18.6 35.56,34.26 34.92,34.9 v1(34.92,37.77) 34.92,40.64 35.56,41.27 U16.6 ; v1(72.09,39.62) U17.54
  IS1 w0.152: v1(72.09,39.62) 71.42,38.96 56.92,38.96 56.34,38.38 35.53,38.38 v1(34.92,37.77)
A6: length 112.3
  TOP w0.152: U17.55 v1(71.42,47.02) ; J1.7 v1(90.81,6.99) ; U16.5 v1(36.83,44.55) 36.83,41.27 36.2,40.64 36.2,34.92 36.83,34.29 U18.5
  IS1 w0.152: 71.42,45.11 v1(71.42,47.02) ; 71.42,45.11 81.92,45.11 82.58,44.45 87.12,44.45 90.32,41.25 90.32,38.71 v1(90.93,38.1) ; 71.42,45.11 68.73,45.11 67.21,43.59 66.45,43.59 66.19,43.84 66.19,44.6 65.94,44.86 37.13,44.86 v1(36.83,44.55)
  IS2 w0.152: v1(90.93,38.1) 90.81,37.97 v1(90.81,6.99)
A7: length 72.6
  TOP w0.152: v1(89.41,39.04) 89.54,38.91 J1.8 ; v1(70.76,44.2) U17.56 ; U18.4 38.1,34.26 37.46,34.9 v1(37.46,37.77) 37.46,40.61 38.1,41.25 U16.4
  IS1 w0.152: v1(70.76,44.2) 71.37,44.81 73.63,44.81 74.3,44.15 84.3,44.15 v1(89.41,39.04)
A8: length 101.9
  TOP w0.152: v1(69.47,44.2) U17.58 ; 88.27,2.54 v1(88.27,6.99) ; U18.3 39.37,34.26 38.73,34.9 38.73,40.61 39.37,41.25 v1(39.37,43.48) U16.3
  IS2 w0.152: v1(69.47,44.2) 69.14,43.87 69.14,29.87 72.03,26.97 72.03,25.81 74.93,22.91 v1(74.93,9.17)
  BOTTOM w0.152: v1(88.27,6.99) 86.08,9.17 v1(74.93,9.17) ; v1(69.47,44.2) 68.2,42.93 56.92,42.93 56.34,43.51 39.4,43.51 v1(39.37,43.48)
A9: length 88.1
  TOP w0.152: J1.10 87,37.64 v1(85.6,39.04) ; v1(68.83,47.02) U17.59 68.83,43.92 v1(70.08,42.67) ; U10.11 v2(41.91,52.07) ; v1(39.37,47.24) 38.76,46.63 38.76,41.45 38.1,40.79 U16.25 38.1,34.9 38.73,34.26 38.73,28.55 38.1,27.91 38.1,23.5
  IS1 w0.152: v1(85.6,39.04) 83.9,39.04 82.88,40.06 82.88,42.34 82.37,42.85 75.49,42.85 74.93,42.29 74.32,42.29 73.94,42.67 v1(70.08,42.67) ; v2(41.91,52.07) 41.91,50.8
A10: length 107.4
  TOP w0.152: 83.19,2.54 v1(83.19,6.99) ; U17.60 68.17,35.66 v1(67.56,35.05) ; 36.83,23.5 v1(36.83,25.7) 37.46,26.34 37.46,34.26 36.83,34.9 U16.24
  IS1 w0.152: v1(67.56,35.05) 68.22,34.39 76.33,34.39 76.89,33.83 82.78,33.83 v1(83.31,34.37)
  IS2 w0.152: v1(83.31,34.37) 82.88,33.93 82.88,17.53 83.19,17.22 v1(83.19,6.99)
  BOTTOM w0.152: v1(67.56,35.05) 60.38,35.05 57.78,32.46 55.93,32.46 55.27,31.8 54.1,31.8 51.59,29.29 40.41,29.29 v1(36.83,25.7)
A11: length 81.1
  TOP w0.152: U17.61 v1(67.51,47.02) ; v1(33.68,46.89) 33.68,41.45 33.02,40.79 U16.21 33.02,34.9 33.66,34.26 33.66,28.55 33.02,27.91 33.02,23.5 ; J1.12 v1(81.92,6.99)
  IS2 w0.152: v1(81.79,38.43) 81.92,38.3 v1(81.92,6.99)
  BOTTOM w0.152: v1(67.51,47.02) 69.42,45.11 72.26,45.11 72.77,44.6 72.77,41.5 75.31,38.96 81.25,38.96 v1(81.79,38.43)
A12: length 79.1
  TOP w0.152: v1(66.88,44.2) U17.62 ; 35.56,23.5 35.56,27.91 36.2,28.55 36.2,34.26 35.56,34.9 U16.23 ; J1.13 v1(80.65,6.99)
  IS1 w0.152: v1(56.64,46.48) 56.72,46.41 65.18,46.41 66.88,44.7 v1(66.88,44.2)
  IS2 w0.152: v1(80.65,6.99) 80.65,36.2 v1(79.5,37.34)
  BOTTOM w0.152: v1(66.88,44.2) 67.49,44.81 71.22,44.81 71.48,44.55 71.48,41.76 75.59,37.64 79.2,37.64 v1(79.5,37.34)
A13: length 98
  TOP w0.152: U18.2 40.64,34.29 40.01,34.92 40.01,43.61 v1(40.64,44.25) U16.2 ; v1(65.58,44.2) U17.64 ; v1(79.5,41.99) 80.11,41.38 80.11,37.08 79.38,36.35 J1.14
  IS1 w0.152: v1(73.41,43.28) 65.99,43.28 65.58,43.69 v1(65.58,44.2)
  BOTTOM w0.152: v1(79.5,41.99) 78.89,41.38 73.51,41.38 73.15,41.73 73.15,43.03 v1(73.41,43.28) ; v1(65.58,44.2) 64.97,43.59 63.83,43.59 63.58,43.84 63.58,44.55 63.32,44.81 41.2,44.81 v1(40.64,44.25)
A14: length 49.7
  TOP w0.152: v1(39.34,39.62) 39.37,39.6 U16.26 39.37,34.9 40.01,34.26 40.01,28.55 39.37,27.91 39.37,23.5 ; U17.65 v1(64.92,47.02)
  IS1 w0.152: v1(65.02,41.91) 63.37,40.26 56.92,40.26 56.29,39.62 v1(39.34,39.62)
  IS2 w0.152: v1(64.92,47.02) 64.92,42.01 v1(65.02,41.91)
A15: length 68.7
  TOP w0.152: U16.27 40.64,34.9 41.27,34.26 41.27,28.55 40.64,27.91 40.64,23.5 ; v1(64.8,36.45) 64.19,37.06 64.19,44.12 v1(64.26,44.2) U17.66 ; J1.16 v1(76.84,6.99)
  IS1 w0.152: v1(73.41,37.34) 72.52,36.45 v1(64.8,36.45)
  IS2 w0.152: v1(73.41,37.34) 73.74,37.01 74.93,37.01 76.84,35.1 v1(76.84,6.99)
A16: length 1.5
  TOP w0.152: v1(61.67,44.2) U17.70
A23: length 30.5
  TOP w0.152: U17.80 v1(57.18,40.94)
  IS1 w0.152: U15.6 83.39,35.13 77.24,35.13 76.58,35.79 62.76,35.79 v1(61.98,36.58)
  IS2 w0.152: v1(61.98,36.58) 61.54,36.58 v1(57.18,40.94)
ADDR0: length 75.8
  TOP w0.152: U4.6 11.43,21.56 10.8,22.2 10.8,27.91 11.43,28.55 U3.6 11.43,34.26 10.8,34.9 10.8,40.61 11.43,41.25 U2.6 11.43,46.96 10.8,47.6 10.8,53.31 11.43,53.95 U1.6 11.43,59.05 12.07,59.69 40.01,59.69 40.01,55.88 39.37,55.24 U10.9
ADDR1: length 77.4
  TOP w0.152: U3.7 10.16,34.26 9.53,34.9 9.53,40.61 10.16,41.25 U2.7 10.16,46.96 9.53,47.6 9.53,53.31 10.16,53.95 U1.7 10.16,59.66 10.8,60.3 40.61,60.3 40.64,60.32 52.07,60.32 52.7,59.69 52.7,56.52 52.07,55.88 U12.9
ADDR2: length 91.7
  TOP w0.152: U13.9 63.5,56.52 64.14,57.15 64.14,60.32 63.5,60.96 8.89,60.96 U1.8 8.89,53.95 8.25,53.31 8.25,47.6 8.89,46.96 U2.8 8.89,41.25 8.25,40.61 8.25,34.9 8.89,34.26 U3.8
ADDR3: length 105.7
  TOP w0.152: U11.9 74.93,55.88 75.57,56.52 75.57,60.96 74.93,61.59 7.62,61.59 U1.9 7.62,53.97 6.99,53.34 6.99,47.6 7.62,46.96 U2.9 7.62,41.25 6.99,40.61 6.99,34.9 7.62,34.26 U3.9
ADDR4: length 125.6
  TOP w0.152: U11.7 76.2,61.9 6.99,61.9 6.99,53.97 6.35,53.34 U1.11 6.35,47.6 6.99,46.96 6.99,41.25 6.35,40.61 U2.11 6.35,34.9 6.99,34.26 6.99,28.55 6.35,27.91 6.35,22.2 6.99,21.56 6.99,15.85 6.35,15.21 U4.11
ADDR5: length 84.9
  TOP w0.152: U1.12 7.62,53.34 8.25,53.97 8.25,61.29 64.14,61.29 64.77,60.66 U13.7 ; 7.62,23.5 7.62,22.2 8.25,21.56 8.25,15.85 7.62,15.21 U4.12
ADDR6: length 71.1
  TOP w0.152: 8.89,23.5 8.89,22.2 9.53,21.56 9.53,15.85 8.89,15.21 U4.13 ; U12.7 53.34,60.32 53.04,60.63 40.44,60.63 40.44,60.6 9.53,60.6 9.53,53.97 8.89,53.34 U1.13
ADDR7: length 55.6
  TOP w0.152: U1.14 10.16,53.34 10.8,53.97 10.8,59.36 11.43,59.99 40.64,59.99 U10.7 ; 10.16,23.5 10.16,22.2 10.8,21.56 10.8,15.85 10.16,15.21 U4.14
ADSL: length 54.2
  TOP w0.152: U17.16 v1(68.17,26.7) 68.17,33.12 73.76,38.71 v1(73.76,41.99) ; J1.24 v1(66.68,6.99)
  IS2 w0.152: v1(66.68,6.99) 66.68,23.47 66.83,23.62 66.83,25.35 v1(68.17,26.7)
  BOTTOM w0.152: U15.3 83.49,42.85 75.54,42.85 74.68,41.99 v1(73.76,41.99)
BHEL: length 44.7
  TOP w0.152: 70.48,2.54 v1(70.48,6.99) ; v1(70.13,23.88) U17.19
  IS2 w0.152: v1(70.13,23.88) 71.09,22.91 71.09,15.09 70.48,14.48 v1(70.48,6.99)
  BOTTOM w0.152: U15.7 83.08,33.76 77.24,33.76 76.58,33.1 74.04,33.1 70.13,29.18 v1(70.13,23.88)
BLEL: length 65.9
  TOP w0.152: U17.17 68.83,26.92 69.24,27.33 v1(74.93,27.33) ; v1(98.43,31.75) J1.1
  IS1 w0.152: U15.8 86.36,30.48 87.63,31.75 v1(98.43,31.75)
  BOTTOM w0.152: U15.8 84.81,29.49 84.81,27.36 84.4,26.95 75.31,26.95 v1(74.93,27.33)
CAS0L: length 100.9
  TOP w0.152: U4.17 13.36,11.4 13.36,21.72 v1(13.97,22.33) 13.97,23.5
  IS1 w0.152: U15.17 92.74,29.24 65.18,29.24 64.49,29.92 56.92,29.92 56.34,30.51 46.76,30.51 v1(46.74,30.48)
  BOTTOM w0.152: v1(46.74,30.48) 16.48,30.48 15.85,29.85 15.85,24.21 v1(13.97,22.33)
CAS1L: length 97.5
  TOP w0.152: v1(13.97,35.03) U2.17 13.36,36.8 13.36,47.73 13.97,48.34 U1.17
  IS1 w0.152: U15.18 87,33.02 85.39,31.42 83.41,31.42 83.24,31.24 58.72,31.24 57.43,32.54 56.92,32.54 56.36,33.1 47.17,33.1 46.15,32.08 45.31,32.08 44.48,32.92 16.08,32.92 v1(13.97,35.03)
CLK2: length 96.2
  TOP w0.152: v1(66.88,41.91) 66.88,27.64 67.51,27 U17.15 v1(67.51,23.88) ; J1.62 v1(15.88,6.99) ; v1(70.48,16.61) 70.48,17.78
  IS1 w0.152: v1(70.48,16.61) 69.88,16 24.89,16 v1(24.13,16.76)
  IS2 w0.152: v1(70.48,16.61) 70.48,20.9 v1(67.51,23.88)
  BOTTOM w0.152: v1(15.88,6.99) 15.88,14.81 17.83,16.76 v1(24.13,16.76)
CLRCNT: length 39.2
  TOP w0.152: U14.12 81.28,15.34 v1(82.55,16.61) U14.2
  IS2 w0.152: v1(82.55,16.61) 82.55,35.81 83.24,36.5 83.74,36.5 84.76,37.52 84.76,39.12 86.28,40.64 U15.21
D0: length 41.7
  TOP w0.152: v1(22.86,19.15) U9.9 ; v1(58.42,23.88) U17.1
  BOTTOM w0.152: v1(58.42,23.88) 58.42,22.4 55.88,19.86 48.87,19.86 47.35,18.34 23.67,18.34 v1(22.86,19.15)
D1: length 39.2
  TOP w0.152: U17.100 v1(57.18,27.94) ; v1(24.13,19.15) U9.8
  IS1 w0.152: v1(57.18,27.94) 56.57,27.33 40.08,27.33 v1(39.98,27.43)
  BOTTOM w0.152: v1(39.98,27.43) 36.4,23.85 28.83,23.85 v1(24.13,19.15)
D2: length 35.6
  TOP w0.152: v1(54.36,28.6) U17.99 ; v1(25.4,19.15) U9.7
  BOTTOM w0.152: v1(54.36,28.6) 45.29,28.6 40.23,23.55 29.79,23.55 v1(25.4,19.15)
D3: length 43.5
  TOP w0.152: v1(26.67,19.15) U9.6 ; U17.96 v1(57.18,30.53)
  IS1 w0.152: v1(57.4,26.67) 29.26,26.67 26.67,24.08 v1(26.67,19.15)
  IS2 w0.152: v1(57.4,26.67) 57.78,27.05 57.78,29.92 v1(57.18,30.53)
D4: length 40
  TOP w0.152: v1(27.94,19.15) U9.5 ; v1(54.36,31.19) U17.95
  IS1 w0.152: v1(27.94,19.15) 27.94,23.77 30.48,26.31 52.35,26.31 v1(52.83,25.83)
  IS2 w0.152: v1(52.83,25.83) 54.97,27.97 54.97,30.58 v1(54.36,31.19)
D5: length 43.7
  TOP w0.152: v1(29.21,19.15) U9.4 ; U17.94 v1(57.18,31.85)
  IS2 w0.152: v1(57.18,31.85) 57.78,32.46 57.78,33.48 57.51,33.76 56.74,33.76 55.27,32.28 55.27,25.91 v1(53.75,24.38)
  BOTTOM w0.152: v1(29.21,19.15) 29.21,20.7 31.75,23.24 43.08,23.24 44.22,24.38 v1(53.75,24.38)
D6: length 37.1
  TOP w0.152: v1(54.36,32.49) U17.93 ; v1(30.48,19.15) U9.3
  IS1 w0.152: v1(51.41,31.24) 52.65,32.49 v1(54.36,32.49)
  IS2 w0.152: v1(51.41,22.86) v1(51.41,31.24)
  BOTTOM w0.152: v1(30.48,19.15) 34.26,22.94 51.33,22.94 v1(51.41,22.86)
D7: length 39.8
  TOP w0.152: v1(31.75,19.15) U9.2 ; U17.92 v1(57.18,33.15)
  IS2 w0.152: v1(57.18,33.15) 55.88,31.85 v1(55.88,21.34)
  BOTTOM w0.152: v1(55.88,21.34) 33.93,21.34 v1(31.75,19.15)
D8: length 61
  TOP w0.152: U17.90 v1(57.18,34.44) ; v1(22.86,57.25) U8.9
  IS2 w0.152: v1(22.86,57.25) 23.47,56.64 23.47,33.93 v1(23.88,33.53)
  BOTTOM w0.152: v1(57.18,34.44) 55.91,33.17 47.22,33.17 46.38,34.01 45.29,34.01 44.81,33.53 v1(23.88,33.53)
D9: length 55
  TOP w0.152: v1(24.13,57.25) U8.8 ; v1(54.36,35.1) U17.89
  IS2 w0.152: v1(24.54,35.81) 24.74,36.02 24.74,56.64 v1(24.13,57.25)
  BOTTOM w0.152: v1(24.54,35.81) 42.19,35.81 43.43,34.57 53.82,34.57 v1(54.36,35.1)
D10: length 56.9
  TOP w0.152: v1(25.4,57.25) U8.7 ; U17.88 v1(57.18,35.74)
  IS1 w0.152: v1(26.16,35.05) 27.61,36.5 46.66,36.5 47.42,35.74 v1(57.18,35.74)
  IS2 w0.152: v1(25.4,57.25) 25.4,50.93 26.01,50.32 26.01,35.2 v1(26.16,35.05)
D11: length 49.8
  TOP w0.152: v1(54.36,36.4) U17.87 ; v1(26.67,57.25) U8.6
  IS2 w0.152: v1(27.91,41.91) 27.28,42.54 27.28,56.64 v1(26.67,57.25)
  BOTTOM w0.152: v1(27.91,41.91) 27.91,37.57 28.93,36.55 54.2,36.55 v1(54.36,36.4)
D12: length 51
  TOP w0.152: v1(27.94,57.25) U8.5 ; U17.86 v1(57.18,37.03)
  IS2 w0.152: v1(28.55,37.97) 28.55,56.64 v1(27.94,57.25)
  BOTTOM w0.152: v1(57.18,37.03) 29.49,37.03 v1(28.55,37.97)
D13: length 2.7
  TOP w0.152: v1(54.36,38.99) U17.83 ; v1(29.21,57.25) U8.4
D14: length 43.8
  TOP w0.152: U17.82 v1(57.18,39.65) ; v1(30.48,57.25) U8.3
  BOTTOM w0.152: v1(30.48,57.25) 30.48,44.65 33.12,42.01 46.89,42.01 49.25,39.65 v1(57.18,39.65)
D15: length 37.7
  TOP w0.152: v1(54.36,40.28) U17.81 ; v1(31.75,57.25) U8.2
  BOTTOM w0.152: v1(54.36,40.28) 53.82,40.28 51.23,42.88 36.93,42.88 34.39,45.42 34.39,49.83 31.75,52.48 v1(31.75,57.25)
DATA0: length 83.2
  TOP w0.152: v1(29.21,31.85) U18.11 ; J1.28 v1(61.59,6.99) ; v1(16.51,9.63) U4.19 ; v1(22.25,15.24) 21.59,14.58 U9.11 v1(21.59,9.63)
  IS1 w0.152: v1(61.59,6.99) 58.34,10.24 22.2,10.24 v1(21.59,9.63)
  IS2 w0.152: v1(22.25,15.24) 22.25,30.23 24.79,32.77 28.3,32.77 v1(29.21,31.85)
  BOTTOM w0.152: v1(21.59,9.63) 20.98,9.02 17.12,9.02 v1(16.51,9.63)
DATA1: length 81
  TOP w0.152: v1(23.11,15.98) 22.86,15.72 U9.12 v1(22.86,9.63) ; 60.32,2.54 v1(60.32,6.99) ; v1(15.24,9.63) U4.18 ; v1(27.94,31.85) U18.12
  IS1 w0.152: 22.86,9.02 v1(22.86,9.63) ; 22.86,9.02 27.41,9.02 30.05,6.38 59.72,6.38 v1(60.32,6.99) ; 22.86,9.02 15.85,9.02 v1(15.24,9.63)
  IS2 w0.152: v1(27.94,31.85) 27.33,32.46 24.99,32.46 23.47,30.94 23.47,16.33 v1(23.11,15.98)
DATA2: length 77.8
  TOP w0.152: v1(24.13,9.63) U9.13 ; v1(16.51,19.15) U4.2 ; v1(26.67,31.85) U18.13 ; J1.30 v1(59.05,6.99)
  IS1 w0.152: v1(59.05,6.99) 58.45,7.59 30.58,7.59 28.55,9.63 v1(24.13,9.63)
  IS2 w0.152: v1(26.67,31.85) 24.74,29.92 24.74,15.24 24.13,14.63 ; v1(16.51,19.15) 16.51,17.27 19.15,14.63 24.13,14.63 ; 24.13,14.63 v1(24.13,9.63)
DATA3: length 64
  TOP w0.152: 26.04,21.18 26.04,21.56 25.4,22.2 25.4,23.5 ; 26.04,21.18 18.64,21.18 U4.1 ; 26.04,21.18 26.04,13.64 v1(25.4,13) U9.14 ; v1(57.4,11.43) 57.78,11.05 57.78,2.54
  IS1 w0.152: v1(25.4,13) 27.48,10.92 56.9,10.92 v1(57.4,11.43)
DATA4: length 61.5
  TOP w0.152: v1(52.07,9.63) 52.22,9.78 53.98,9.78 56.52,7.24 J1.32 ; 16.51,23.5 16.51,23.75 17.12,24.36 26.06,24.36 26.67,23.75 26.67,22.2 27.3,21.56 27.3,13.64 v1(26.67,13) U9.15
  BOTTOM w0.152: v1(26.67,13) 29.06,10.62 51.08,10.62 v1(52.07,9.63)
DATA5: length 70.8
  TOP w0.152: v1(15.24,22.33) 15.24,23.5 ; U9.16 v1(27.94,13) 28.57,13.64 28.57,21.56 27.94,22.2 27.94,23.75 26.54,25.15 v1(25.4,25.15) ; 55.24,2.54 v1(55.24,6.99)
  IS1 w0.152: v1(27.94,13) 28.55,12.4 52.58,12.4 v1(55.42,15.24) ; v1(25.4,25.15) 18.06,25.15 v1(15.24,22.33)
  IS2 w0.152: v1(55.24,6.99) 55.42,7.16 v1(55.42,15.24)
DATA6: length 65.6
  TOP w0.152: J1.34 v1(53.98,6.99) ; U3.2 16.51,29.13 19.05,26.59 26.92,26.59 29.21,24.31 29.21,22.2 29.84,21.56 29.84,13.64 v1(29.21,13) U9.17
  BOTTOM w0.152: v1(29.21,13) 31.29,10.92 52.2,10.92 53.98,9.14 v1(53.98,6.99)
DATA7: length 61.4
  TOP w0.152: v1(30.73,9.14) 30.48,9.4 U9.18 30.48,15.21 31.11,15.85 31.11,21.56 30.48,22.2 30.48,24.66 23.29,31.85 18.95,31.85 U3.1 ; v1(52.98,9.17) 52.7,8.89 52.7,2.54
  IS1 w0.152: v1(30.73,9.14) 30.86,9.02 52.83,9.02 v1(52.98,9.17)
DATA8: length 89.6
  TOP w0.152: U8.11 v1(21.59,47.73) 21.59,43.79 16.51,38.71 U2.19 ; v1(29.21,44.55) U16.11 ; J1.36 v1(51.44,6.99)
  IS1 w0.152: v1(52.07,42.9) 52.04,42.88 30.89,42.88 v1(29.21,44.55)
  IS2 w0.152: v1(52.07,42.9) 52.07,12.4 51.44,11.76 v1(51.44,6.99)
  BOTTOM w0.152: v1(21.59,47.73) 22.2,48.34 25.43,48.34 v1(29.21,44.55)
DATA9: length 88
  TOP w0.152: v1(27.94,44.55) U16.12 ; v1(22.86,47.73) U8.12 ; U2.18 v1(15.24,43.43) ; 50.16,2.54 v1(50.16,6.99)
  IS1 w0.152: v1(47.5,42.27) 29.84,42.27 28.17,43.94 27.94,43.94 ; 22.86,43.94 27.94,43.94 ; 22.86,43.94 v1(22.86,47.73) ; 22.86,43.94 22.35,43.43 v1(15.24,43.43) ; 27.94,43.94 v1(27.94,44.55)
  IS2 w0.152: v1(47.5,42.27) 50.16,39.6 v1(50.16,6.99)
DATA10: length 82.6
  TOP w0.152: v1(24.13,47.73) U8.13 ; v1(26.67,44.55) U16.13 ; v1(16.51,44.55) U2.2 ; J1.38 v1(48.89,6.99)
  IS1 w0.152: v1(46.74,46.48) 46.41,46.15 28.27,46.15 v1(26.67,44.55)
  IS2 w0.152: v1(48.89,6.99) 48.89,33.55 46.74,35.71 v1(46.74,46.48)
  BOTTOM w0.152: v1(16.51,44.55) 17.68,45.72 24.66,45.72 ; 24.66,45.72 24.66,47.19 v1(24.13,47.73) ; 24.66,45.72 25.5,45.72 v1(26.67,44.55)
DATA11: length 81.4
  TOP w0.152: 47.62,2.54 47.62,33.83 v1(47.5,33.96) ; v1(25.4,50.06) U8.14 25.4,47.6 26.04,46.96 26.04,41.25 25.4,40.61 U16.15 25.4,34.92 26.04,34.29 v1(27.53,34.29) ; v1(17.78,44.55) U2.1
  IS1 w0.152: v1(25.4,50.06) 24.23,50.06 22.2,48.03 22.2,47.45 19.3,44.55 v1(17.78,44.55) ; v1(47.5,33.96) 29.08,33.96 28.7,33.58 28.24,33.58 v1(27.53,34.29)
DATA12: length 76.3
  TOP w0.152: 26.67,37.36 26.67,40.61 27.3,41.25 27.3,46.96 26.67,47.6 U8.15 v1(26.67,50.06) ; 26.67,37.36 U16.16 ; 26.67,37.36 v1(27.28,37.36) ; J1.40 v1(46.35,6.99) ; v1(16.51,47.73) U1.19
  IS1 w0.152: v1(16.51,47.73) 19.46,50.67 26.06,50.67 v1(26.67,50.06)
  IS2 w0.152: v1(33.93,9.63) 29.87,13.69 29.87,34.77 v1(27.28,37.36)
  BOTTOM w0.152: v1(46.35,6.99) 43.71,9.63 v1(33.93,9.63)
DATA13: length 81.6
  TOP w0.152: v1(43.79,35.81) 43.79,20.83 45.09,19.53 J1.41 ; v1(15.24,47.73) U1.18 ; v1(28.45,34.29) 28.45,35.69 U16.17 27.94,40.61 28.57,41.25 28.57,46.96 27.94,47.6 U8.16 v1(27.94,50.06)
  IS1 w0.152: v1(28.45,34.29) 29.97,35.81 v1(43.79,35.81)
  BOTTOM w0.152: v1(15.24,47.73) 18.19,50.67 27.33,50.67 v1(27.94,50.06)
DATA14: length 72.3
  TOP w0.152: U1.2 16.51,54.53 19.05,51.99 26.92,51.99 29.21,49.71 U8.17 29.21,47.6 29.84,46.96 29.84,41.25 29.21,40.61 U16.18 29.21,34.34 29.92,33.63 29.92,26.82 32.41,24.33 32.41,18.39 43.81,6.99 J1.42
DATA15: length 75.3
  TOP w0.152: v1(33.02,31.85) 31.5,31.85 31.19,32.16 31.19,33.63 30.81,34.01 30.81,35.86 U16.19 30.48,40.61 31.11,41.25 31.11,46.96 30.48,47.6 U8.18 29.97,49.4 29.97,54.1 27.43,56.64 19.56,56.64 U1.1 ; J1.43 v1(42.55,6.99)
  IS2 w0.152: v1(33.02,31.85) 38.3,31.85 42.55,27.61 v1(42.55,6.99)
HLDA: length 36.7
  TOP w0.152: J1.25 v1(65.41,6.99) ; v1(59.72,23.88) U17.3 ; U6.1 v1(53.34,18.95)
  IS2 w0.152: v1(59.72,23.88) 64.8,18.8 64.8,16.36 65.41,15.75 v1(65.41,6.99)
  BOTTOM w0.152: v1(53.34,18.95) 58.09,18.95 59.72,20.57 v1(59.72,23.88)
MIO: length 49.1
  TOP w0.152: J1.23 67.95,8.86 71.09,12.01 71.09,19.56 72.72,21.18 U17.23 v1(72.72,26.7)
  IS2 w0.152: U15.5 82.88,39.04 74.24,39.04 72.72,37.52 v1(72.72,26.7)
MUXS0L: length 13.6
  BOTTOM w0.152: U15.20 92.43,39.65 v1(81.03,39.65)
PCLK: length 115
  TOP w0.152: J1.64 v1(13.34,6.99) ; U15.2 84.81,44.73 84.81,19.68 84.07,18.95 v1(83.82,18.95) U14.1 ; U7.6 v1(67.95,18.95)
  BOTTOM w0.152: v1(83.82,18.95) 83.21,18.34 67.95,18.34 ; 67.95,18.34 67.13,17.53 16.36,17.53 14.33,15.49 14.33,7.98 v1(13.34,6.99) ; 67.95,18.34 v1(67.95,18.95)
RA0: length 42.4
  TOP w0.152: v6(50.16,48.89) 50.8,48.26 U6.3 ; U10.12 v6(43.18,51.43)
  BOTTOM w0.152: v6(50.16,48.89) 46.51,48.89 46.15,49.25 45.29,49.25 44.93,48.89 44.45,48.89 43.18,50.16 v6(43.18,51.43)
RA3: length 10.8
  TOP w0.152: v1(46.99,16.61) U6.6 ; v1(52.07,11.53) U6.13
  BOTTOM w0.152: v1(46.99,16.61) 46.99,14.4 49.86,11.53 v1(52.07,11.53)
RA6: length 1.2
  TOP w0.152: v1(46.99,11.53) U6.9
RA7: length 1.2
  TOP w0.152: v1(45.72,11.53) U6.8
RASL: length 123.1
  TOP w0.152: 14.58,45.16 14.58,31.85 ; 14.58,45.16 14.58,57.25 13.97,57.86 U1.4 ; 14.58,45.16 14.53,45.16 U2.4 ; 14.58,31.85 v1(13.97,31.85) U3.4 ; 14.58,31.85 14.58,20.93 U4.4
  IS1 w0.152: v1(13.97,31.85) 14.58,31.24 41.27,31.24 43.23,29.29 56.26,29.29 56.92,28.63 83.16,28.63 83.41,28.88 93.04,28.88 U15.16
RDYL: length 108.1
  TOP w0.152: v1(62.33,23.88) U17.7 ; J1.60 18.41,18.16 v1(18.54,18.29)
  IS1 w0.152: v1(18.54,18.29) 59.28,18.29 62.33,21.34 v1(62.33,23.88)
  BOTTOM w0.152: v1(62.33,23.88) 62.33,33.88 62.84,34.39 74.85,34.39 76.81,36.35 83.19,36.35 83.39,36.55 92.99,36.55 U15.19
REF: length 40.6
  TOP w0.152: v1(76.2,11.53) U14.8 ; U17.4 v1(60.38,26.7)
  IS1 w0.152: v1(60.38,26.7) 61.67,25.4 75.59,25.4 ; 75.59,25.4 75.59,12.14 v1(76.2,11.53) ; 75.59,25.4 U15.10
RESET: length 93.2
  TOP w0.152: v1(74.68,32.49) U17.33 ; v1(20.07,13.59) 20.07,9.14 22.22,6.99 22.22,2.54 ; U5.1 v1(63.5,18.95)
  IS2 w0.152: v1(61.21,16.61) 61.21,16.66 v1(63.5,18.95)
  BOTTOM w0.152: 78.11,27.94 78.11,29.06 v1(74.68,32.49) ; 78.11,27.94 74.35,27.94 73.33,26.92 73.33,22.86 70.03,19.56 64.11,19.56 v1(63.5,18.95) ; 78.11,27.94 U15.9 ; v1(20.07,13.59) 20.09,13.61 34.8,13.61 38.4,17.22 60.6,17.22 v1(61.21,16.61)
RESETL: length 10.3
  TOP w0.152: v1(62.23,16.61) U5.2 ; U7.5 v1(69.22,18.95)
  IS1 w0.152: v1(69.22,18.95) 67.49,17.22 62.84,17.22 v1(62.23,16.61)
ROMOEL: length 76.3
  TOP w0.152: U15.15 92.68,26.7 v1(92.68,27.33) ; U16.22 34.29,34.9 34.92,34.26 34.92,26.34 v1(34.29,25.7) 34.29,23.5
  IS1 w0.152: v1(92.68,27.33) 92.35,27 83.41,27 82.47,27.94 60.76,27.94 59.69,26.87 59.69,26.37 58.42,25.1 34.9,25.1 v1(34.29,25.7)
UN1F39330PQ0: length 12
  TOP w0.152: v1(77.47,16.61) U14.6 ; v1(82.55,11.53) U14.13
  BOTTOM w0.152: v1(77.47,16.61) 81.69,16.61 82.55,15.75 v1(82.55,11.53)
UN127C25637PVPP0: length 13.2
  TOP w0.152: U16.1 41.91,41.25 41.27,40.61 41.27,34.9 41.91,34.26 U18.1
WEL: length 124.8
  TOP w0.152: 15.85,32.46 15.8,32.46 U3.3 ; 15.85,32.46 15.85,44.55 ; 15.85,32.46 15.85,20.93 U4.3 ; 15.85,44.55 v1(15.24,44.55) U2.3 ; 15.85,44.55 15.85,57.25 15.24,57.86 U1.3
  IS1 w0.152: v1(82.27,41.91) 81.74,41.38 70.51,41.38 69.37,42.52 58.75,42.52 57.78,41.55 55.22,41.55 54.97,41.3 16.41,41.3 14.63,43.08 14.63,43.94 v1(15.24,44.55)
  BOTTOM w0.152: U15.22 92.71,41.91 v1(82.27,41.91)
WR: length 128.4
  TOP w0.152: v1(74.02,26.7) U17.25 75.54,23.88 75.54,11.38 71.76,7.59 70.23,7.59 69.22,6.58 J1.22 ; v1(33.02,19.15) U9.1 ; v1(33.02,57.25) U8.1
  IS1 w0.152: v1(33.02,19.15) 47.6,19.15 48.01,19.56 59.08,19.56 61.62,22.1 61.62,24.23 61.87,24.49 72.57,24.49 73.94,23.11 v1(73.94,22.86)
  IS2 w0.152: v1(33.02,19.15) 32.41,19.76 32.41,56.64 v1(33.02,57.25)
  BOTTOM w0.152: 74.63,22.86 U15.11 ; 74.63,22.86 v1(73.94,22.86) ; 74.63,22.86 74.63,26.09 v1(74.02,26.7)

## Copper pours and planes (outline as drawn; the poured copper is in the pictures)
GND on GND (solid shape): 96.52,60.96 99.06,58.42 100.33,58.42 100.33,6.99 99.06,6.99 99.06,6.35 98.43,5.71 87,5.71 86.36,6.35 86.36,7.62 83.82,7.62 83.82,6.35 83.19,5.71 22.22,5.71 21.59,6.35 21.59,7.62 19.05,7.62 19.05,6.35 18.41,5.71 4.45,5.71 4.45,8.26 2.54,10.16 1.27,10.16 1.27,57.15 6.35,62.23 96.52,62.23
VCC on VCC (solid shape): 100.33,57.15 100.33,8.26 99.06,6.99 99.06,6.35 87,6.35 86.36,6.99 86.36,7.62 83.82,7.62 83.82,6.35 22.22,6.35 21.59,6.99 21.59,7.62 19.05,7.62 19.05,6.35 5.08,6.35 4.45,6.99 4.45,8.26 1.27,11.43 1.27,57.15 6.35,62.23 95.25,62.23

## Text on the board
COMMON_BAR: ADDR7 | ADDR6 | ADDR5
